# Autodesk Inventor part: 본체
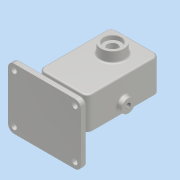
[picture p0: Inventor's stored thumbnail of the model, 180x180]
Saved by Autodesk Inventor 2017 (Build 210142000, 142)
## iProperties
Part Number: 본체
Material: 알루미늄 6061
Document SubType Name: Modeling
Designer: MRC
Density: 2.7 g/cm^3
Appearance: 알루미늄 - 평지
Mass: 1472.54 g
Surface Area: 818.394 cm^2
Volume: 545.387 cm^3
Author: MRC
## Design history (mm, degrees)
sketch "스케치1"
  geometry: L1 (-40, 60)-(40, 60); L2 (40, 60)-(40, -60); L3 (40, -60)-(-40, -60); L4 (-40, -60)-(-40, 60); 3 further points
  constraints: 8 end point, 2 midpoint, 2 parallel, 1 horizontal, 1 horizontal alignment, 1 perpendicular, 1 vertical alignment
  dimensions: "d0" = 80 distance of L1.start L1.end; "d1" = 120 distance of L1.end L2.end
extrude "돌출1" new body sketch "스케치1" distance "d3" = 39; taper "d5" = 0 deg; dims "d4" = 14, "d6" = 0
sketch "스케치3"
  geometry: L1 (0, 22)-(0, -22); L2 (-24, 22)-(-24, -22); L3 (24, -22)-(24, 22); A1 r 24 centre (0, 22) between (24, 22) and (-24, 22); A2 r 24 centre (0, -22) between (-24, -22) and (24, -22); 2 further points
  constraints: 8 end point, 4 point on circle, 4 tangent, 2 centre point, 1 coincident, 1 midpoint, 1 parallel, 1 vertical
  dimensions: "d9" = 24 radius of A1; "d11" = 44 distance of L1.end L1.start
extrude "돌출2" cut sketch "스케치3" distance "d12" = 29; taper "d13" = 0 deg
sketch "스케치4"
  geometry: C1 r 12.5 at (0, 22); C2 r 12.5 at (0, -22); A1 r 24 centre (0, -22) between (-24, -22) and (24, -22) reference; A2 r 24 centre (0, 22) between (24, 22) and (-24, 22) reference; 1 further point
  constraints: 2 centre point, 2 coincident
  dimensions: "d14" = 25 diameter of C1; "d17" = 25 diameter of C2
extrude "돌출3" cut sketch "스케치4" distance "d15" = 15; taper "d16" = 0 deg
sketch "스케치5"
  geometry: C1 r 12.5 at (0, 22) reference; C2 r 19 at (0, 22); 1 further point
  constraints: 1 centre point, 1 coincident
  dimensions: "d18" = 38 diameter of C2
extrude "돌출4" join sketch "스케치5" distance "d19" = 17; taper "d20" = 0 deg
hole "구멍1" diameter "d23" = 17; stored, may be unused: countersink angle "d27" = 90 deg, drill point angle "d29" = 118 deg; dims "d21" = 10, "d22" = 10, "d24" = 6, "d25" = 28, "d26" = 7.3, "d28" = 8
fillet "모깎기1" dims "d30" = 9
sketch "스케치6"
  geometry: C1 r 11 at (-39, 51); 1 further point
  constraints: 1 centre point, 1 coincident
  dimensions: "d31" = 22 diameter of C1
extrude "돌출5" join sketch "스케치6" distance "d32" = 8; taper "d33" = 0 deg
sketch "스케치7"
  geometry: C1 r 11 at (-14, 51); 1 further point
  constraints: 1 centre point, 1 coincident
  dimensions: "d34" = 22 diameter of C1
extrude "돌출6" join sketch "스케치7" distance "d35" = 8; taper "d36" = 0 deg
hole "구멍2" diameter "d39" = 8.376; stored, may be unused: countersink angle "d43" = 90 deg, drill point angle "d45" = 118 deg; dims "d40" = 96, "d41" = 28, "d42" = 7.3, "d44" = 27.3, "d48" = 10, "d49" = 10
sketch "스케치8"
  geometry: L1 (-80, 56)-(-90, 56); L2 (-90, 56)-(-90, -44); L3 (-90, -44)-(-80, -44); L4 (-80, -44)-(-80, 56); L5 (8, 56)-(36, 56) reference; 2 further points
  constraints: 8 end point, 2 parallel, 1 horizontal, 1 midpoint, 1 perpendicular, 1 point on line
  dimensions: "d46" = 10 distance of L1.start L1.end; "d47" = 90 distance from line of point (0, 0) L2; "d50" = 100 distance of L1.end L2.end
extrude "돌출7" join sketch "스케치8" stored distance "d51" = 120; taper "d52" = 0 deg
sketch "스케치10"
  geometry: L1 (-80, -14)-(-60, -2.453); L2 (-60, -2.453)-(-60, 27.453); L3 (-60, 27.453)-(-80, 39); L4 (-80, -44)-(-80, 56) reference; L5 (-60, 39)-(-60, -14) reference; L6 (-80, 39)-(-80, -14); 2 further points
  constraints: 8 end point, 2 midpoint, 1 equal length, 1 point on line, 1 vertical
  dimensions: "d56" = 53 distance of L3.end L1.start; "d58" = 60 deg angle of L4 L1; "d59" = 60 deg angle of L4 L3; "d60" = 17 distance of L4.end L3.end
extrude "돌출8" join sketch "스케치10" stored distance "d61" = 48; taper "d62" = 0 deg
chamfer "모따기1" distance "d63" = 0.7; stored, may be unused: second distance "d64" = 2, angle "d65" = 30 deg
fillet "모깎기2" dims "d66" = 10
fillet "모깎기3" dims "d67" = 0.5
sketch "스케치11"
  geometry: A1 r 9 centre (31, -51) between (31, -60) and (40, -51) reference; A2 r 9 centre (31, 51) between (40, 51) and (31, 60) reference; A3 r 9 centre (-31, 51) between (-31, 60) and (-40, 51) reference; A4 r 9 centre (-31, -51) between (-40, -51) and (-31, -60) reference; 9 further points
  constraints: 4 coincident, 4 vertical alignment
  dimensions: "d68" = 44 distance of point (-31, -22) point (-31, 22); "d69" = 22 vertical distance of point (0, 0) point (-31, 22); "d70" = 44 distance of point (31, -22) point (31, 22); "d71" = 22 vertical distance of point (0, 0) point (31, 22)
hole "구멍3" sketch "스케치11" at (-31, 51), (31, 51), (31, -51), (-31, -51), (-31, -22), (-31, 22), (31, 22), (31, -22) diameter "d72" = 4.134; stored, may be unused: countersink angle "d76" = 90 deg, drill point angle "d78" = 118 deg; dims "d73" = 10, "d74" = 28, "d75" = 7.3, "d77" = 12
sketch "스케치12"
  geometry: C1 r 4.5 at (100, 10); C2 r 4.5 at (0, 10); C3 r 4.5 at (100, 90); C4 r 4.5 at (0, 90); A1 r 10 centre (0, 90) between (0, 100) and (-10, 90) reference; A2 r 10 centre (0, 10) between (-10, 10) and (0, 0) reference; A3 r 10 centre (100, 10) between (100, 0) and (110, 10) reference; A4 r 10 centre (100, 90) between (110, 90) and (100, 100) reference; 1 further point
  constraints: 4 centre point, 4 coincident
  dimensions: "d79" = 9 diameter of C1; "d80" = 9 diameter of C2; "d81" = 9 diameter of C3; "d82" = 9 diameter of C4
extrude "돌출9" cut sketch "스케치12" distance "d83" = 48; taper "d84" = 0 deg
sketch "스케치13"
  geometry: L1 (110, 90)-(110, 10) reference; L2 (0, 100)-(100, 100) reference; 2 further points
  constraints: 1 other
  dimensions: "d85" = 60 distance from line of L1 point (50, 90); "d86" = 10 distance from line of point (50, 90) L2
feature "엠보싱1" sketch "스케치13" dims "d0" = 80, "d1" = 120, "d87" = 0.5, "d88" = 0
fillet "모깎기4" dims "d89" = 3
fillet "모깎기5" dims "d90" = 3
chamfer "모따기2" distance "d91" = 1; stored, may be unused: second distance "d92" = 2, angle "d93" = 30 deg
node "솔리드1"
